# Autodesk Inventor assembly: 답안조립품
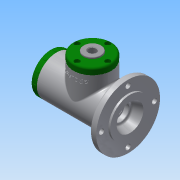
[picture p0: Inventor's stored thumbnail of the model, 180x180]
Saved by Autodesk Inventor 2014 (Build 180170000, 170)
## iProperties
Created: 2016-08
Part Number: 답안조립품
Document SubType Name: Assembly
Designer: 703-04
Author: 703-04
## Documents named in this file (7)
- C:\Users\703-04\Desktop\460808V1013\답안조립품.iam
- C:\Users\703-04\Desktop\460808V1013\본체.ipt
- C:\Users\703-04\Desktop\460808V1013\사이드 커버.ipt
- 사이드 커버.ipt
- C:\Users\703-04\Desktop\460808V1013\탑 커버.ipt
- 탑 커버.ipt
- C:\Users\703-04\Desktop\460808V1013\탑 부시.ipt
